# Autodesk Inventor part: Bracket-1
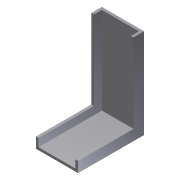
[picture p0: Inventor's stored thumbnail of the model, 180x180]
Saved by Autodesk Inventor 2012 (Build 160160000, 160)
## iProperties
Shininess: 77.0
Length Units: 11269
Angle Units: 11279
Time Units: 11290
Mass Units: 11283
Length Display Precision: 3
Angle Display Precision: 2
Created: 2002-04
Part Number: Bracket-1
Document SubType Name: Modeling
Density: 1 g/cm^3
Material: Default
Density: 0.0
Volumn: 0.0
Area: 0.0
PropertySet Name: Model Information
Control State: 0
Master: False
Checked Out: False
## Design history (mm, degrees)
node "Sketch1"
sketch "Sketch2"
  geometry: L1 (-4.258, 23.699)-(-4.258, -18.801); L2 (-4.258, -18.801)-(26.992, -18.801); L3 (26.992, -18.801)-(26.992, -13.801); L4 (26.992, -13.801)-(0.742, -13.801); L5 (0.742, -13.801)-(0.742, 23.699); L6 (0.742, 23.699)-(-4.258, 23.699)
  constraints: 12 end point, 4 parallel, 2 perpendicular, 1 vertical
  dimensions: "d0" = 31.25 distance of L1.end L2.end; "d1" = 42.5 distance of L1.start L1.end; "d2" = 5 distance of L2.end L3.end
extrude "Extrusion1" new body sketch "Sketch2" stored distance "d3" = 20; taper "d4" = 0 deg
shell "Shell1" dims "d5" = 1.25
body "Solid1"
